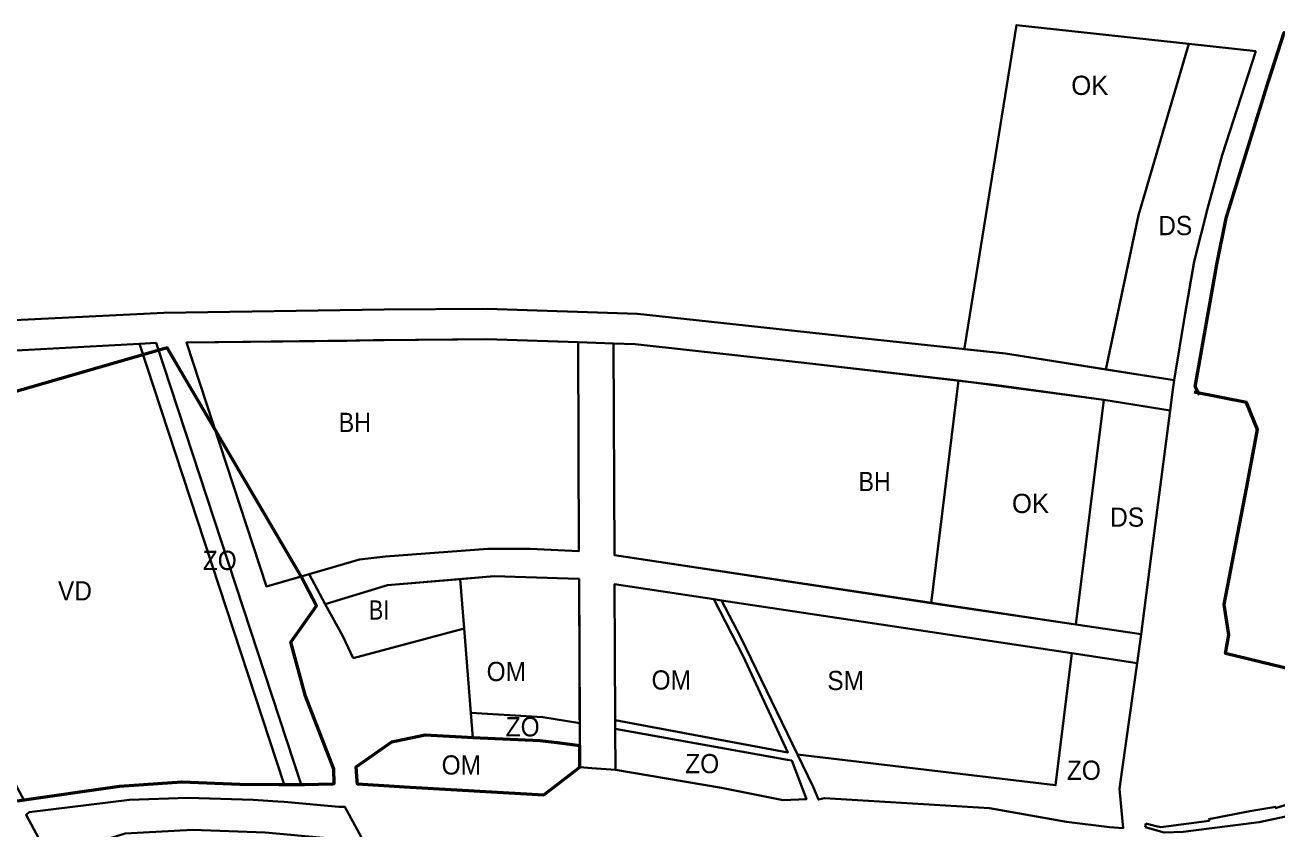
# Model space of a CAD drawing. Extents: x -650276 to -642489, y -1074311 to -1066658.
# Drawn here: x -647428 to -646647, y -1069855 to -1069353 of the extents above; entities that cross this region are included whole.
import ezdxf

# ---------------------------------------------------------------- set-up
doc = ezdxf.new("R2010")
doc.units = 0
doc.header["$LTSCALE"] = 4.8
for name, color, linetype, lineweight in [('1', 7, 'Continuous', 35), ('12', 7, 'Continuous', 35), ('13', 7, 'Continuous', 35), ('15', 7, 'Continuous', 35), ('18', 7, 'Continuous', 35), ('2', 7, 'Continuous', 35), ('24', 7, 'Continuous', 35), ('25', 7, 'Continuous', 35), ('35', 7, 'Continuous', 35), ('42', 7, 'Continuous', 35), ('60', 7, 'Continuous', 53)]:
    doc.layers.add(name, color=color, linetype=linetype, lineweight=lineweight)
doc.layers.add('62', color=7, linetype='Continuous')

msp = doc.modelspace()

# ---------------------------------------------------------------- linework, layer by layer
at = {"layer": '1'}
for points in [[(-647251.002, -1069695.852), (-647219.628, -1069686.746), (-647203.374, -1069684.716), (-647139.649, -1069679.961), (-647113.255, -1069679.966), (-647082.761, -1069681.399), (-647083.356, -1069551.018), (-647140.247, -1069549.071), (-647158.572, -1069549.252), (-647211.05, -1069549.77), (-647227.623, -1069550.23), (-647327.682, -1069551.263), (-647277.71, -1069703.421)], [(-646944.168, -1069563.743), (-647047.648, -1069552.245), (-647061.304, -1069551.773), (-647060.7, -1069683.894), (-646863, -1069714), (-646846, -1069575)]]:
    msp.add_lwpolyline(points, close=True, dxfattribs=at)
at = {"layer": '12'}
for points in [[(-647150.138, -1069782.334), (-647105.334, -1069785.168), (-647082.271, -1069788.81), (-647082.682, -1069698.791), (-647089.456, -1069698.579), (-647135.585, -1069697.137), (-647156.782, -1069698.901), (-647154.33, -1069729.69)], [(-647060.23, -1069786.932), (-646952.56, -1069807.13), (-646980.4, -1069746.98), (-646998.56, -1069711.443), (-647060.617, -1069702.116)]]:
    msp.add_lwpolyline(points, close=True, dxfattribs=at)
for points in [[(-647107.04, -1069799.84), (-647148.9, -1069797.88), (-647148.9, -1069797.88), (-647178.73, -1069796.4), (-647196.616, -1069800.068)], [(-647196.616, -1069800.068), (-647199.65, -1069800.69), (-647221.87, -1069816.21), (-647221.28, -1069824.74), (-647221.14, -1069826.761), (-647191.66, -1069828.58), (-647201.106, -1069827.997), (-647191.66, -1069828.58), (-647104.741, -1069833.568)], [(-647082.206, -1069802.916), (-647107.04, -1069799.84), (-647107.04, -1069799.84)], [(-647104.741, -1069833.568), (-647082.145, -1069816.321), (-647082.206, -1069802.916)]]:
    msp.add_lwpolyline(points, dxfattribs=at)
at = {"layer": '13'}
for points in [[(-646816.615, -1069558.064), (-646754.066, -1069567.993), (-646733.74, -1069471.688), (-646733.74, -1069471.688), (-646702.425, -1069364.771), (-646702.425, -1069364.771), (-646702.425, -1069364.771), (-646702.425, -1069364.771), (-646702.425, -1069364.771), (-646809.879, -1069353.002), (-646842.103, -1069553.182), (-646842.441, -1069555.283), (-646816.615, -1069558.064)], [(-646772.906, -1069727.176), (-646755.269, -1069587.04), (-646846, -1069575), (-646863, -1069714)]]:
    msp.add_lwpolyline(points, close=True, dxfattribs=at)
at = {"layer": '15'}
for points in [[(-647433.779, -1069556.106), (-647356.899, -1069552.034), (-647346.554, -1069551.486), (-647256.034, -1069827.107), (-647235.49, -1069826.51), (-647235.62, -1069817.62), (-647253.45, -1069771.95), (-647262.46, -1069738.25), (-647259.11, -1069733.52), (-647253.97, -1069726.27), (-647246.42, -1069715.63), (-647249.555, -1069709.677), (-647256.061, -1069697.32), (-647277.71, -1069703.421), (-647327.682, -1069551.263), (-647204.208, -1069549.647), (-647140.247, -1069549.071), (-647083.356, -1069551.018), (-647061.304, -1069551.773), (-647047.702, -1069552.239), (-646944.167, -1069563.743), (-646822.169, -1069577.72), (-646755.269, -1069587.04), (-646714.037, -1069593.585), (-646712.34, -1069580.49), (-646711.444, -1069574.771), (-646711.442, -1069574.759), (-646816.615, -1069558.064), (-646910.029, -1069548.006), (-646986.633, -1069539.757), (-647046.325, -1069533.275), (-647140.008, -1069530.068), (-647204.293, -1069530.647), (-647341.697, -1069532.602), (-647434.969, -1069537.141)], [(-647083.356, -1069551.018), (-647082.761, -1069681.399), (-647113.255, -1069679.966), (-647139.649, -1069679.961), (-647203.374, -1069684.716), (-647219.628, -1069686.746), (-647251.002, -1069695.852), (-647240.994, -1069714.513), (-647202.181, -1069702.678), (-647135.585, -1069697.137), (-647089.456, -1069698.579), (-647082.682, -1069698.791), (-647082.145, -1069816.321)], [(-647060.617, -1069702.116), (-646998.56, -1069711.443), (-646993.771, -1069712.163), (-646775.286, -1069745.022), (-646734.48, -1069751.35), (-646732.143, -1069733.308), (-646772.906, -1069727.176), (-646842.148, -1069716.763), (-647060.7, -1069683.894), (-647061.304, -1069551.773), (-647083.356, -1069551.018)], [(-647082.145, -1069816.321), (-647082.145, -1069816.321), (-647074.72, -1069816.8), (-647060.029, -1069817.854), (-647060.206, -1069792.294), (-647060.23, -1069786.932), (-647060.617, -1069702.116)], [(-647082.206, -1069802.916), (-647107.04, -1069799.84), (-647148.9, -1069797.88), (-647148.9, -1069797.88), (-647178.73, -1069796.4), (-647196.616, -1069800.068)], [(-647196.616, -1069800.068), (-647199.65, -1069800.69), (-647221.87, -1069816.21), (-647221.28, -1069824.74), (-647221.14, -1069826.761), (-647205.603, -1069827.72), (-647191.66, -1069828.58), (-647201.106, -1069827.997), (-647191.66, -1069828.58), (-647104.741, -1069833.568)], [(-647104.741, -1069833.568), (-647082.145, -1069816.321), (-647082.206, -1069802.916)]]:
    msp.add_lwpolyline(points, dxfattribs=at)
msp.add_lwpolyline([(-647217.177, -1069862.57), (-647228.77, -1069840.98), (-647232.66, -1069841.07), (-647266.62, -1069837.86), (-647270.71, -1069837.61), (-647285.9, -1069836.66), (-647326.71, -1069835.46), (-647363.21, -1069836.64), (-647425.73, -1069844.31), (-647427.62, -1069845.94), (-647413.461, -1069872.442), (-647365.866, -1069857.774), (-647323.794, -1069855.468), (-647278.525, -1069857.002), (-647239.912, -1069860.654)], close=True, dxfattribs=at)
at = {"layer": '18'}
msp.add_lwpolyline([(-646785.437, -1069827.534), (-646775.286, -1069745.022), (-646993.771, -1069712.163), (-646981.92, -1069734.86), (-646946.369, -1069808.291)], close=True, dxfattribs=at)
at = {"layer": '2'}
msp.add_lwpolyline([(-647223.66, -1069748.26), (-647154.33, -1069729.69), (-647156.782, -1069698.901), (-647202.181, -1069702.678), (-647240.994, -1069714.513), (-647230.16, -1069734.42)], close=True, dxfattribs=at)
at = {"layer": '24'}
msp.add_line((-646772.907, -1069727.177), (-646732.143, -1069733.308), dxfattribs=at)
msp.add_lwpolyline([(-646660.526, -1069369.36), (-646702.425, -1069364.771), (-646733.74, -1069471.688), (-646754.066, -1069567.993), (-646711.442, -1069574.759), (-646704.68, -1069533.06), (-646699.07, -1069500.57), (-646690.51, -1069466.97), (-646681.5, -1069434.17)], close=True, dxfattribs=at)
for points in [[(-646725.82, -1069684.5), (-646714.037, -1069593.585), (-646755.269, -1069587.04), (-646772.907, -1069727.177)], [(-646732.143, -1069733.308), (-646725.82, -1069684.5), (-646725.82, -1069684.5)]]:
    msp.add_lwpolyline(points, dxfattribs=at)
at = {"layer": '25'}
msp.add_line((-646729.54, -1069853.69), (-646729.24, -1069851.41), dxfattribs=at)
for points in [[(-646515.63, -1069810.24), (-646522.32, -1069812.28), (-646560.92, -1069825.33), (-646613.65, -1069840.02), (-646620.06, -1069841.69), (-646629.83, -1069844.23), (-646635.93, -1069845.82), (-646658.5, -1069850.59), (-646689.73, -1069854.58), (-646705.87, -1069856.62), (-646717.66, -1069857.11), (-646729.54, -1069853.69)], [(-646729.24, -1069851.41), (-646723.5, -1069852.83), (-646719.82, -1069853.78), (-646689.63, -1069849.7), (-646689.8, -1069848.71), (-646664.22, -1069843.72), (-646648.18, -1069841.04), (-646648.28, -1069841.78), (-646638.34, -1069838.73), (-646623.31, -1069834.1)]]:
    msp.add_lwpolyline(points, dxfattribs=at)
at = {"layer": '35'}
for points in [[(-647356.899, -1069552.034), (-647433.779, -1069556.106), (-647433.779, -1069556.106), (-647513.66, -1069562.249), (-647514.067, -1069562.282), (-647560.836, -1069566.036), (-647563.104, -1069566.28)], [(-647369.3, -1069828.22), (-647330.46, -1069825.51), (-647294.38, -1069826.88), (-647270.09, -1069827.02), (-647266.581, -1069827.042), (-647356.899, -1069552.034)], [(-647521.943, -1069665.763), (-647428.993, -1069836.714), (-647369.3, -1069828.22)]]:
    msp.add_lwpolyline(points, dxfattribs=at)
at = {"layer": '42'}
msp.add_line((-647266.581, -1069827.042), (-647256.034, -1069827.107), dxfattribs=at)
for points in [[(-647256.034, -1069827.107), (-647346.554, -1069551.486), (-647356.899, -1069552.034), (-647266.581, -1069827.042)], [(-647082.271, -1069788.81), (-647105.334, -1069785.168), (-647105.334, -1069785.168), (-647150.138, -1069782.334), (-647148.9, -1069797.88), (-647107.04, -1069799.84)], [(-647107.04, -1069799.84), (-647082.206, -1069802.916), (-647082.271, -1069788.81)]]:
    msp.add_lwpolyline(points, dxfattribs=at)
for points in [[(-646775.286, -1069745.022), (-646785.437, -1069827.534), (-646946.369, -1069808.291), (-646936.6, -1069828.47), (-646933.39, -1069836.51), (-646929.67, -1069835.68), (-646826.63, -1069841.84), (-646778.74, -1069850.44), (-646751.8, -1069853.72), (-646743.31, -1069854.26), (-646743.7, -1069850.07), (-646745.56, -1069829.84), (-646743.85, -1069817.72), (-646734.48, -1069751.35)], [(-646993.81, -1069829.12), (-646993.81, -1069829.12), (-646955.45, -1069836.93), (-646940.94, -1069836.34), (-646950.08, -1069812.16), (-646952.68, -1069811.69), (-647060.206, -1069792.294), (-647060.029, -1069817.854)]]:
    msp.add_lwpolyline(points, close=True, dxfattribs=at)
at = {"layer": '60'}
for points in [[(-646695.61, -1069583.8), (-646698.4, -1069578.93), (-646684.95, -1069502.53), (-646679.13, -1069473.51), (-646652.72, -1069388.08), (-646642.89, -1069357.68), (-646580.797, -1069364.111), (-646557.39, -1069519.61), (-646548.41, -1069582.03), (-646569.86, -1069690.67), (-646581.489, -1069759.421), (-646585.51, -1069769.57), (-646619.49, -1069764.46), (-646622, -1069759.34), (-646679.46, -1069745.37), (-646677.36, -1069733.65), (-646680.28, -1069714.83), (-646673, -1069676.8), (-646666.26, -1069641.2), (-646659.52, -1069605.53), (-646666.36, -1069588.57), (-646698.96, -1069582.26)], [(-647433.32, -1069837.33), (-647369.3, -1069828.22), (-647330.46, -1069825.51), (-647294.38, -1069826.88), (-647270.09, -1069827.02), (-647253.88, -1069827.12), (-647236.5, -1069826.63), (-647235.49, -1069826.51), (-647235.62, -1069817.62), (-647253.45, -1069771.95), (-647262.46, -1069738.25), (-647253.97, -1069726.27), (-647247.86, -1069717.66), (-647246.42, -1069715.63), (-647256.061, -1069697.32), (-647339.58, -1069554.46), (-647375.71, -1069564.91), (-647499.63, -1069600.73)]]:
    msp.add_lwpolyline(points, dxfattribs=at)
msp.add_lwpolyline([(-647196.616, -1069800.068), (-647199.65, -1069800.69), (-647221.87, -1069816.21), (-647221.28, -1069824.74), (-647221.14, -1069826.761), (-647201.106, -1069827.997), (-647191.66, -1069828.58), (-647104.741, -1069833.568), (-647082.145, -1069816.321), (-647082.206, -1069802.916), (-647096.39, -1069801.15), (-647107.04, -1069799.84), (-647148.9, -1069797.88), (-647152.39, -1069797.7), (-647178.73, -1069796.4)], close=True, dxfattribs=at)

# ---------------------------------------------------------------- texts
at = {"layer": '62'}
for p in [(-646775.694, -1069396.644), (-646812.694, -1069657.644)]:
    msp.add_text('OK', height=12, dxfattribs=at).set_placement(p)
for s, width, p in [('DS', 0.95, (-646721.423, -1069484.188)), ('BH', 0.9, (-647232.617, -1069607.053)), ('BH', 0.9, (-646908.386, -1069643.937)), ('DS', 0.95, (-646751.423, -1069666.188)), ('ZO', 0.95, (-647317.423, -1069693.188)), ('VD', 0.95, (-647407.767, -1069712.204)), ('BI', 0.85, (-647213.92, -1069724.163)), ('OM', 0.95, (-647140.377, -1069762.527)), ('OM', 0.95, (-647037.483, -1069767.845)), ('SM', 0.95, (-646927.837, -1069768.153)), ('ZO', 0.95, (-647128.473, -1069797.058)), ('OM', 0.95, (-647168.433, -1069820.895)), ('ZO', 0.95, (-647016.473, -1069820.058)), ('ZO', 0.95, (-646778.423, -1069824.188))]:
    msp.add_text(s, height=12, dxfattribs=dict(at, width=width)).set_placement(p)

doc.saveas('drawing.dxf')
